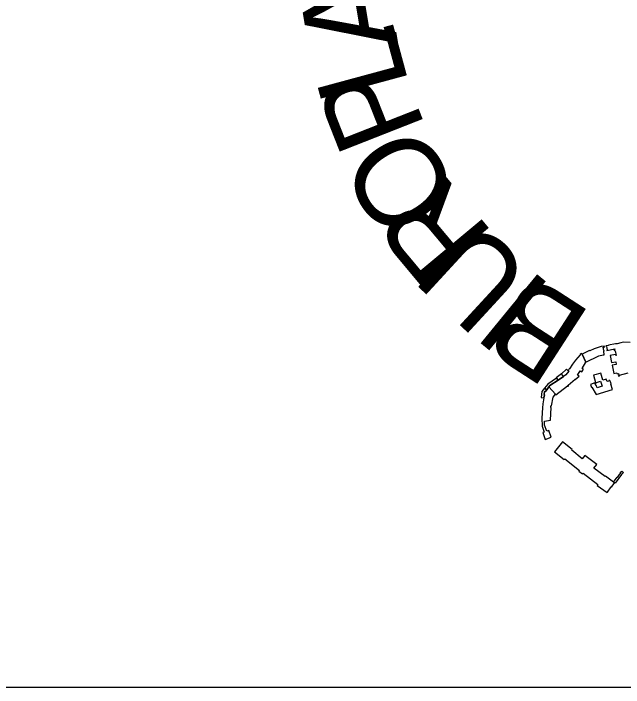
# Model space of a CAD drawing. Extents: x -293619 to -291580, y 30940 to 32770.
# Drawn here: x -291667.41 to -291643.62, y 30940.41 to 30966.7 of the extents above; entities that cross this region are included whole.
import ezdxf

# ---------------------------------------------------------------- set-up
doc = ezdxf.new("R2010")
doc.units = 0
doc.layers.add('RAMKA_I_OPISY', color=7, linetype='Continuous')

msp = doc.modelspace()

# ---------------------------------------------------------------- linework, layer by layer
at = {"layer": 'RAMKA_I_OPISY'}
for points in [[(-293607.614, 32757.815), (-291589.506, 32757.815), (-291589.506, 30940.411), (-293607.614, 30940.411)], [(-291644.372, 30953.726), (-291644.499, 30953.706), (-291644.761, 30953.621), (-291644.936, 30953.541), (-291644.943, 30953.547), (-291645.231, 30953.407), (-291645.088, 30953.093), (-291644.585, 30953.346), (-291644.412, 30953.379), (-291644.378, 30953.386), (-291644.395, 30953.522), (-291644.38, 30953.526), (-291644.382, 30953.551), (-291644.395, 30953.553), (-291644.412, 30953.679), (-291644.368, 30953.686)], [(-291645.088, 30953.093), (-291645.231, 30953.407), (-291645.256, 30953.439), (-291645.256, 30953.439), (-291645.313, 30953.392), (-291645.307, 30953.382), (-291645.5, 30953.172), (-291645.611, 30953.024), (-291645.728, 30952.836), (-291645.738, 30952.839), (-291645.783, 30952.765), (-291645.759, 30952.741), (-291645.878, 30952.6), (-291645.96, 30952.543), (-291646.175, 30952.39), (-291646.494, 30952.182), (-291646.531, 30952.13), (-291646.278, 30951.846), (-291646.257, 30951.829), (-291645.807, 30952.177), (-291645.786, 30952.151), (-291645.765, 30952.167), (-291645.787, 30952.195), (-291645.512, 30952.43), (-291645.503, 30952.424), (-291645.358, 30952.547), (-291645.421, 30952.594), (-291645.31, 30952.758), (-291645.248, 30952.721), (-291645.184, 30952.82), (-291645.241, 30952.857)], [(-291646.035, 30952.643), (-291645.851, 30952.823), (-291645.783, 30952.765), (-291645.759, 30952.741), (-291645.878, 30952.6), (-291645.96, 30952.543)], [(-291646.698, 30952.08), (-291646.608, 30952.017), (-291646.531, 30952.13), (-291646.494, 30952.182), (-291646.175, 30952.39), (-291646.236, 30952.477), (-291646.57, 30952.242)], [(-291646.236, 30952.477), (-291646.175, 30952.39), (-291645.96, 30952.543), (-291646.035, 30952.643), (-291646.243, 30952.489)], [(-291644.693, 30951.831), (-291644.054, 30952.037), (-291644.116, 30952.238), (-291644.103, 30952.257), (-291644.125, 30952.33), (-291644.144, 30952.338), (-291644.161, 30952.387), (-291644.194, 30952.377), (-291644.191, 30952.361), (-291644.265, 30952.339), (-291644.296, 30952.44), (-291644.426, 30952.398), (-291644.506, 30952.665), (-291644.689, 30952.615), (-291644.793, 30952.586), (-291644.712, 30952.299), (-291644.707, 30952.296), (-291644.699, 30952.279), (-291644.67, 30952.287), (-291644.672, 30952.299), (-291644.514, 30952.353), (-291644.458, 30952.161), (-291644.647, 30952.091), (-291644.689, 30952.198), (-291644.704, 30952.192), (-291644.735, 30952.29), (-291644.915, 30952.23), (-291644.877, 30952.112), (-291644.857, 30952.118)], [(-291646.698, 30952.08), (-291646.803, 30951.951), (-291646.836, 30951.725), (-291646.728, 30951.706), (-291646.704, 30951.822), (-291646.721, 30951.837), (-291646.7, 30951.936), (-291646.67, 30951.967), (-291646.648, 30951.965), (-291646.608, 30952.017)], [(-291646.368, 30951.739), (-291646.278, 30951.846), (-291646.531, 30952.13), (-291646.608, 30952.017), (-291646.648, 30951.965), (-291646.67, 30951.967), (-291646.7, 30951.936), (-291646.721, 30951.837), (-291646.704, 30951.822), (-291646.728, 30951.706), (-291646.773, 30951.467), (-291646.788, 30951.322), (-291646.803, 30950.909), (-291646.798, 30950.605), (-291646.715, 30950.371), (-291646.767, 30950.353), (-291646.674, 30950.081), (-291646.441, 30950.176), (-291646.533, 30950.437), (-291646.619, 30950.406), (-291646.704, 30950.644), (-291646.699, 30950.801), (-291646.468, 30950.831), (-291646.445, 30951.324), (-291646.462, 30951.33), (-291646.459, 30951.391), (-291646.436, 30951.4)], [(-291645.999, 30949.991), (-291646.309, 30949.6), (-291645.937, 30949.309), (-291645.915, 30949.335), (-291645.334, 30948.88), (-291645.359, 30948.85), (-291645.218, 30948.739), (-291645.195, 30948.767), (-291644.623, 30948.324), (-291644.646, 30948.294), (-291644.264, 30948.011), (-291644.25, 30948.031), (-291644.253, 30948.034), (-291644.108, 30948.232), (-291644.097, 30948.225), (-291643.974, 30948.391), (-291644.013, 30948.422), (-291644.328, 30948.659), (-291644.343, 30948.64), (-291644.776, 30948.969), (-291644.666, 30949.108), (-291645.128, 30949.458), (-291645.232, 30949.33), (-291645.643, 30949.667), (-291645.62, 30949.697)], [(-291643.954, 30948.377), (-291643.974, 30948.391), (-291644.013, 30948.422), (-291643.869, 30948.611), (-291643.862, 30948.605), (-291643.776, 30948.718), (-291643.783, 30948.724), (-291643.752, 30948.764), (-291643.695, 30948.715)], [(-291643.752, 30948.764), (-291643.689, 30948.846), (-291643.629, 30948.797), (-291643.695, 30948.715)]]:
    msp.add_lwpolyline(points, close=True, dxfattribs=at)
msp.add_lwpolyline([(-291643.363, 30953.863), (-291643.631, 30953.873), (-291643.729, 30953.852), (-291643.733, 30953.847), (-291643.875, 30953.815), (-291643.894, 30953.807), (-291643.93, 30953.813), (-291644.208, 30953.759), (-291644.208, 30953.752), (-291644.308, 30953.733), (-291644.301, 30953.703), (-291644.283, 30953.703), (-291644.261, 30953.581), (-291644.275, 30953.578), (-291644.27, 30953.549), (-291643.959, 30953.612), (-291643.957, 30953.593), (-291643.984, 30953.587), (-291643.995, 30953.562), (-291643.946, 30953.534), (-291643.908, 30953.362), (-291643.921, 30953.361), (-291643.932, 30953.395), (-291644.139, 30953.363), (-291644.089, 30953.087), (-291643.923, 30953.112), (-291643.905, 30953.008), (-291644.07, 30952.975), (-291644.006, 30952.658), (-291643.885, 30952.685), (-291643.869, 30952.638), (-291643.823, 30952.657), (-291643.808, 30952.6), (-291643.825, 30952.566), (-291643.796, 30952.551), (-291643.778, 30952.588), (-291643.443, 30952.686)], dxfattribs=at)
msp.add_lwpolyline([(-291643.363, 30953.863), (-291643.631, 30953.873), (-291643.729, 30953.852), (-291643.733, 30953.847), (-291643.875, 30953.815), (-291643.894, 30953.807), (-291643.93, 30953.813), (-291644.208, 30953.759), (-291644.208, 30953.752), (-291644.308, 30953.733), (-291644.301, 30953.703), (-291644.283, 30953.703), (-291644.261, 30953.581), (-291644.275, 30953.578), (-291644.27, 30953.549), (-291643.959, 30953.612), (-291643.957, 30953.593), (-291643.984, 30953.587), (-291643.995, 30953.562), (-291643.946, 30953.534), (-291643.908, 30953.362), (-291643.921, 30953.361), (-291643.932, 30953.395), (-291644.139, 30953.363), (-291644.089, 30953.087), (-291643.923, 30953.112), (-291643.905, 30953.008), (-291644.07, 30952.975), (-291644.006, 30952.658), (-291643.885, 30952.685), (-291643.869, 30952.638), (-291643.823, 30952.657), (-291643.808, 30952.6), (-291643.825, 30952.566), (-291643.796, 30952.551), (-291643.778, 30952.588), (-291643.443, 30952.686)], dxfattribs=at)

# ---------------------------------------------------------------- texts
for s, rotation, p in [('A', 99.3751, (-291652.408, 30965.515)), ('L', 105.152, (-291651.973, 30963.917)), ('P', 111.4777, (-291651.315, 30962.226)), ('O', 123.0281, (-291649.874, 30959.554)), ('R', 129.8494, (-291648.632, 30958.043)), ('U', 137.3667, (-291647.068, 30956.561)), ('I', 140.6609, (-291646.323, 30955.979)), ('B', 147.1186, (-291644.773, 30954.966))]:
    msp.add_text(s, height=3.477, rotation=rotation, dxfattribs=at).set_placement(p)

doc.saveas('drawing.dxf')
